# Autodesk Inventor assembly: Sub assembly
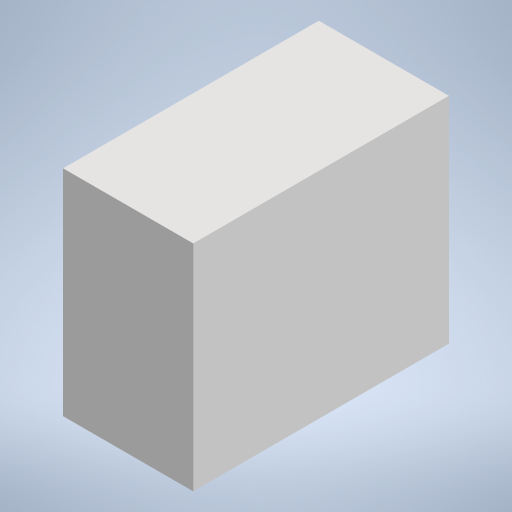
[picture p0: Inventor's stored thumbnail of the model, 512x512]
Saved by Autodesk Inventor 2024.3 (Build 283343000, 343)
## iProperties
Created: 2024-12
Part Number: Sub assembly
Document SubType Name: Assembly
Designer: ruhr
Author: ruhr
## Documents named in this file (2)
- C:\Users\ruhr\OneDrive - Mercantec\Dokumenter\DigiTwinVideo\Sub assembly.iam
- C:\Users\ruhr\OneDrive - Mercantec\Dokumenter\DigiTwinVideo\Part2.ipt
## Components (1 placed, 1 different names)
1. Part2:1
